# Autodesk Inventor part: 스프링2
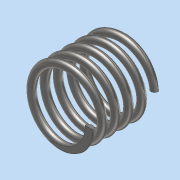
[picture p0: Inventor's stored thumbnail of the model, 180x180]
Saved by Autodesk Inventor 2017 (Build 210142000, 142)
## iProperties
Part Number: 스프링2
Material: 스테인레스 스틸
Document SubType Name: Modeling
Designer: MRC
Density: 8 g/cm^3
Appearance: 반연마
Mass: 6.55763 g
Surface Area: 16.7052 cm^2
Volume: 0.819704 cm^3
Author: MRC
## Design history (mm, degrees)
sketch "스케치1"
  geometry: L1 (0, 0)-(0, 17.5); L2 (0, 0)-(8.5, 0); L3 (0, 17.5)-(7.5, 17.5); C1 r 1 at (8.5, 0)
  constraints: 6 end point, 2 horizontal, 1 centre point, 1 coincident, 1 vertical
  dimensions: "d0" = 17.5 distance of L1.start L1.end (derived); "d1" = 2 diameter of C1; "d2" = 17 diameter of L2.end L1
feature "코일1" sketch "스케치1" pitch "d3" = 10; turns "d5" = 5; dims "d4" = 17.5 (= d0), "d6" = 0, angle "d7" = 90 deg, angle "d8" = 90 deg, "d9" = 0, "d10" = 0
sketch "스케치2"
  geometry: L1 (17.5, 18.5)-(0, 18.5); L2 (0, 18.5)-(0, -18.5); L3 (0, -18.5)-(17.5, -18.5); L4 (17.5, -18.5)-(17.5, 18.5); 2 further points
  constraints: 8 end point, 2 parallel, 1 coincident, 1 horizontal, 1 midpoint, 1 perpendicular
  dimensions: "d11" = 37 distance of L3.end L1.start; "d12" = 17.5 distance of L2.end L3.end (= d0)
extrude "돌출1" sketch "스케치2" stored distance "d13" = 0; taper "d14" = 0 deg
node "솔리드1"
